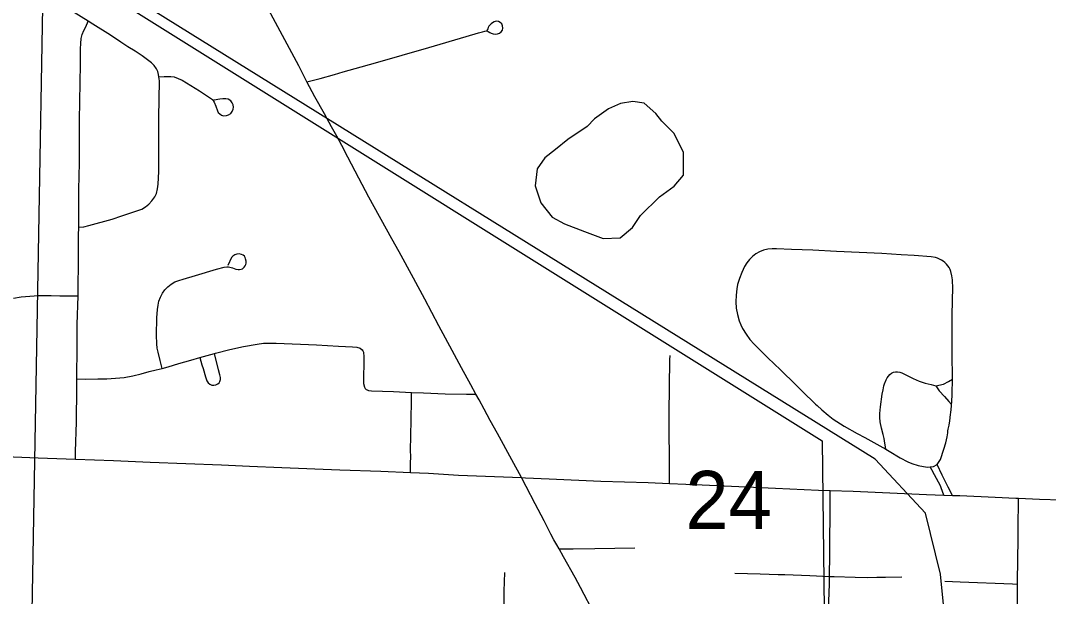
# Model space of a CAD drawing. Extents: x -59 to 43, y 0 to 22.
# Drawn here: x 24.177 to 24.918, y 17.75 to 18.165 of the extents above; entities that cross this region are included whole.
import ezdxf

# ---------------------------------------------------------------- set-up
doc = ezdxf.new("R2010")
doc.units = 0
for name, color, linetype in [('Default', 7, 'Continuous'), ('GM_X_City_Street', 7, 'Continuous'), ('GM_X_Minor_Lake', 7, 'Continuous'), ('GM_X_Rail_Line', 7, 'Continuous'), ('GM_X_Section', 7, 'Continuous'), ('GM_X_Section_Text', 7, 'Continuous'), ('GM_X_State_Route', 7, 'Continuous'), ('GM_X_Township_Road', 7, 'Continuous')]:
    doc.layers.add(name, color=color, linetype=linetype)

msp = doc.modelspace()

# ---------------------------------------------------------------- linework, layer by layer
at = {"layer": 'Default'}
msp.add_lwpolyline([(23.51667, 18.36457), (23.51667, 17.35203), (23.63449, 17.34676), (24.1786, 17.34343), (24.19635, 18.35229)], close=True, dxfattribs=at)
at = {"layer": 'GM_X_City_Street'}
for points in [[(24.21923, 18.01617), (24.22292, 18.01639), (24.22658, 18.01727), (24.24324, 18.02195), (24.2503, 18.02427), (24.26172, 18.02803), (24.26457, 18.02913), (24.2672, 18.03066), (24.26961, 18.03271), (24.27187, 18.03505), (24.27407, 18.0379), (24.27516, 18.04038), (24.27596, 18.0436), (24.27641, 18.04702), (24.27694, 18.05627), (24.27683, 18.06727), (24.27697, 18.08204), (24.27689, 18.09519), (24.27732, 18.12143), (24.27704, 18.12445), (24.27674, 18.12608), (24.27609, 18.12818), (24.27519, 18.13012), (24.27351, 18.13253), (24.27154, 18.13451), (24.2679, 18.1373), (24.26488, 18.13947), (24.25991, 18.14276), (24.25463, 18.14608), (24.24959, 18.14942), (24.24778, 18.15064), (24.24371, 18.15318), (24.24204, 18.15446), (24.22944, 18.16224), (24.22605, 18.16437), (24.21591, 18.17074)], [(24.21681, 17.84902), (24.217, 17.85448), (24.2177, 17.87552), (24.21784, 17.90028), (24.21784, 17.90684), (24.21809, 17.93044), (24.21814, 17.93977), (24.21808, 17.94589), (24.2188, 17.96653), (24.219, 17.99637), (24.2191, 18.00996), (24.21923, 18.01617), (24.21938, 18.0431), (24.21975, 18.0624), (24.21983, 18.07558), (24.21976, 18.09305), (24.22054, 18.13351), (24.22054, 18.14461), (24.22062, 18.14849), (24.22092, 18.1519), (24.22171, 18.15488), (24.22292, 18.15774), (24.22423, 18.16052), (24.22605, 18.16437)], [(24.38365, 18.12071), (24.39323, 18.1233), (24.40359, 18.1261), (24.40968, 18.12792), (24.41844, 18.13029), (24.43301, 18.13436), (24.47142, 18.14549), (24.49835, 18.15341), (24.50729, 18.15605), (24.51005, 18.15675), (24.51188, 18.15725), (24.51309, 18.15748), (24.51424, 18.15699), (24.51531, 18.15638), (24.51646, 18.15587), (24.51787, 18.15545), (24.51942, 18.15519), (24.52096, 18.15526), (24.5224, 18.15577), (24.52361, 18.15672), (24.52444, 18.15801), (24.52479, 18.15952), (24.52464, 18.16106), (24.524, 18.16247), (24.52293, 18.16359), (24.52153, 18.16424), (24.52001, 18.16437), (24.51853, 18.164), (24.51725, 18.16319), (24.51638, 18.16251), (24.5154, 18.16169), (24.51477, 18.16085), (24.51431, 18.1599), (24.51387, 18.15902), (24.51324, 18.15778)], [(24.27704, 18.12445), (24.28067, 18.12465), (24.28285, 18.12463), (24.28546, 18.12458), (24.28796, 18.1243), (24.29093, 18.12319), (24.2937, 18.1219), (24.30611, 18.11432), (24.31554, 18.10803), (24.31604, 18.10735), (24.31674, 18.10605), (24.31792, 18.10318), (24.31911, 18.09986), (24.3197, 18.09875), (24.3208, 18.09773), (24.32215, 18.09685), (24.32358, 18.09638), (24.3256, 18.09646), (24.32718, 18.09689), (24.32873, 18.09793), (24.32984, 18.09931), (24.33039, 18.10098), (24.33063, 18.10252), (24.33047, 18.10415), (24.32987, 18.10573), (24.32869, 18.10712), (24.32694, 18.10819), (24.32528, 18.10863), (24.32309, 18.10862), (24.32092, 18.10838), (24.31684, 18.10747)], [(24.27922, 17.91432), (24.27782, 17.91995), (24.27634, 17.92596), (24.2758, 17.929), (24.27548, 17.93208), (24.27535, 17.93826), (24.27555, 17.95065), (24.276, 17.95679), (24.27635, 17.95986), (24.27698, 17.96288), (24.27803, 17.96577), (24.27948, 17.96848), (24.28134, 17.97095), (24.28349, 17.97313), (24.28588, 17.97505), (24.28856, 17.97658), (24.29144, 17.97768), (24.29439, 17.97862), (24.30333, 17.98119), (24.31835, 17.98592), (24.32406, 17.98737), (24.3258, 17.98751), (24.32714, 17.98741), (24.32996, 17.98683), (24.33231, 17.98589), (24.33412, 17.98549), (24.33502, 17.98549), (24.33622, 17.98571), (24.33712, 17.98611), (24.3385, 17.98727), (24.33915, 17.98814), (24.33955, 17.98922), (24.33973, 17.9902), (24.33977, 17.99168), (24.33947, 17.99335), (24.33908, 17.99422), (24.33853, 17.99508), (24.33763, 17.99584), (24.33643, 17.99649), (24.33478, 17.99685), (24.33321, 17.99671), (24.33172, 17.99613), (24.33032, 17.99519), (24.32939, 17.99412), (24.32667, 17.98842)], [(24.83761, 17.84503), (24.84009, 17.84882), (24.84262, 17.85616), (24.84384, 17.86061), (24.84485, 17.86509), (24.84531, 17.86796), (24.84543, 17.86924), (24.84565, 17.87056), (24.84627, 17.87347), (24.84684, 17.87651), (24.84742, 17.88101), (24.8476, 17.88254), (24.84798, 17.88704), (24.84808, 17.88824), (24.84822, 17.89008), (24.84861, 17.89603), (24.84869, 17.90655), (24.8487, 17.90823), (24.84849, 17.92371), (24.84855, 17.95167), (24.8488, 17.96409), (24.84893, 17.97185), (24.84866, 17.97806), (24.84828, 17.98114), (24.84757, 17.98416), (24.84701, 17.9856), (24.84627, 17.98696), (24.84439, 17.98942), (24.8433, 17.99053), (24.84211, 17.99152), (24.84081, 17.99236), (24.83943, 17.99308), (24.83799, 17.99368), (24.83651, 17.99414), (24.83347, 17.99472), (24.82109, 17.99578), (24.81178, 17.99616), (24.79785, 17.99706), (24.76527, 17.9986), (24.74821, 17.99954), (24.73271, 18.00005), (24.72186, 18.00059), (24.71875, 18.00054), (24.71566, 18.00023), (24.71264, 17.99956), (24.70975, 17.99841), (24.70704, 17.9969), (24.70458, 17.99502), (24.70242, 17.99279), (24.70055, 17.99031), (24.69891, 17.98768), (24.69686, 17.98349), (24.69521, 17.97913), (24.69391, 17.97466), (24.69331, 17.97162), (24.69284, 17.96699), (24.69272, 17.96233), (24.69296, 17.95768), (24.69374, 17.95309), (24.69502, 17.94862), (24.69618, 17.94573), (24.69756, 17.94296), (24.7, 17.93899), (24.70276, 17.93524), (24.70585, 17.93176), (24.7158, 17.92195), (24.72474, 17.91334), (24.73586, 17.90249), (24.74359, 17.8949), (24.74684, 17.89163), (24.75006, 17.88852), (24.75116, 17.8875), (24.75449, 17.8845), (24.75917, 17.88063), (24.76284, 17.87783), (24.76537, 17.87603), (24.7706, 17.8727), (24.78007, 17.86745), (24.78553, 17.86451), (24.79639, 17.85851), (24.80068, 17.85603), (24.8031, 17.85463), (24.81106, 17.84981), (24.81654, 17.84692), (24.81944, 17.84582), (24.82412, 17.84438), (24.83038, 17.84306), (24.83263, 17.8433), (24.83498, 17.84356), (24.83761, 17.84503)], [(24.17221, 17.96499), (24.17763, 17.9659), (24.18409, 17.96645), (24.19015, 17.9668), (24.19934, 17.96686), (24.20553, 17.96673), (24.21171, 17.96664), (24.2188, 17.96653)], [(24.21784, 17.90684), (24.22413, 17.90666), (24.23302, 17.90685), (24.2394, 17.90685), (24.24579, 17.90723), (24.25189, 17.90778), (24.25819, 17.90889), (24.26414, 17.91034), (24.27001, 17.91206), (24.27492, 17.91327), (24.27922, 17.91432), (24.28354, 17.91538), (24.29145, 17.91778), (24.29995, 17.92024), (24.30638, 17.92207), (24.31697, 17.92509), (24.31781, 17.92533), (24.32813, 17.9279), (24.33794, 17.93022), (24.34784, 17.93179), (24.35237, 17.93244), (24.35802, 17.93263), (24.36139, 17.93251), (24.39054, 17.93126), (24.40632, 17.93043), (24.41646, 17.92999), (24.41969, 17.9296), (24.42187, 17.92886), (24.42344, 17.92776), (24.42394, 17.9271), (24.42446, 17.92609), (24.42474, 17.92276), (24.42447, 17.90342), (24.42502, 17.90083), (24.42557, 17.89988), (24.42625, 17.89925), (24.42702, 17.89879), (24.42796, 17.89848), (24.43003, 17.89815), (24.44599, 17.89771), (24.45896, 17.89707), (24.46766, 17.89664), (24.48328, 17.89602), (24.4986, 17.89578), (24.50541, 17.89566)], [(24.30638, 17.92207), (24.30798, 17.91698), (24.30885, 17.91423), (24.31046, 17.90822), (24.31157, 17.90529), (24.31239, 17.904), (24.31359, 17.90297), (24.31505, 17.90228), (24.31648, 17.90214), (24.31807, 17.90239), (24.31935, 17.9032), (24.32036, 17.90405), (24.32098, 17.90499), (24.32135, 17.90624), (24.32129, 17.90775), (24.32098, 17.90962), (24.31984, 17.91342), (24.31697, 17.92509)], [(24.64478, 17.83143), (24.64477, 17.83697), (24.64467, 17.88186), (24.64514, 17.92056), (24.64524, 17.92365)], [(24.80068, 17.85603), (24.79968, 17.86221), (24.79943, 17.86374), (24.79873, 17.86674), (24.7976, 17.87124), (24.79674, 17.87579), (24.79647, 17.87887), (24.79647, 17.88196), (24.79689, 17.88659), (24.79809, 17.89577), (24.79872, 17.89879), (24.79931, 17.9018), (24.79972, 17.90328), (24.80092, 17.90614), (24.80168, 17.90749), (24.80256, 17.90876), (24.80359, 17.90992), (24.80479, 17.91089), (24.80617, 17.91157), (24.80767, 17.91195), (24.8092, 17.91198), (24.81072, 17.91169), (24.81218, 17.91116), (24.82046, 17.90695), (24.82472, 17.90512), (24.82914, 17.90369), (24.83335, 17.90267), (24.83678, 17.90174)], [(24.83678, 17.90174), (24.84217, 17.90306), (24.84582, 17.90501), (24.84869, 17.90655)], [(24.83678, 17.90174), (24.83925, 17.89829), (24.84305, 17.89418), (24.84614, 17.89052), (24.84808, 17.88824)], [(24.45814, 17.8393), (24.45825, 17.84554), (24.45837, 17.85115), (24.45833, 17.85493), (24.45868, 17.87704), (24.45888, 17.89141), (24.45896, 17.89707)], [(24.84253, 17.82303), (24.84054, 17.8282), (24.84, 17.82962), (24.83874, 17.83238), (24.83589, 17.83776), (24.83384, 17.84125), (24.83263, 17.8433)], [(24.84873, 17.82283), (24.84574, 17.8288), (24.84357, 17.83314), (24.84125, 17.8374), (24.83761, 17.84503)], [(24.75783, 17.57509), (24.75775, 17.5809), (24.75755, 17.5963), (24.75766, 17.61436), (24.75805, 17.63606), (24.7582, 17.64534), (24.75857, 17.66365), (24.75905, 17.67897), (24.75936, 17.69707), (24.75975, 17.71576), (24.75976, 17.72499), (24.75984, 17.73114), (24.75964, 17.73728), (24.75976, 17.74655), (24.76007, 17.75889), (24.76013, 17.76445), (24.76035, 17.78052), (24.7604, 17.7866), (24.76046, 17.79422), (24.76061, 17.8051), (24.76064, 17.82032), (24.76066, 17.82639)], [(24.89354, 17.56934), (24.8936, 17.57423), (24.89369, 17.58232), (24.894, 17.60899), (24.89474, 17.64881), (24.89508, 17.6762), (24.89525, 17.69113), (24.89533, 17.69816), (24.89549, 17.73313), (24.89562, 17.75894), (24.89562, 17.76112), (24.89597, 17.79158), (24.89608, 17.80215), (24.89622, 17.81695), (24.89626, 17.82077)], [(24.56525, 17.78433), (24.57097, 17.78438), (24.57545, 17.78441), (24.59109, 17.78465), (24.6199, 17.78508)], [(24.52524, 17.70669), (24.52531, 17.71158), (24.52542, 17.72027), (24.52559, 17.72977), (24.52552, 17.73956), (24.52565, 17.74904), (24.52572, 17.75395), (24.52611, 17.76733)], [(24.69186, 17.76672), (24.7102, 17.76631), (24.72311, 17.76592), (24.728, 17.76579), (24.74587, 17.76505), (24.76013, 17.76445), (24.76359, 17.76431), (24.77851, 17.76388), (24.78777, 17.76371), (24.79434, 17.76383), (24.80047, 17.76395), (24.81223, 17.76408)], [(24.84327, 17.76107), (24.85418, 17.76055), (24.89201, 17.75908), (24.89562, 17.75894)]]:
    msp.add_lwpolyline(points, dxfattribs=at)
at = {"layer": 'GM_X_Minor_Lake'}
msp.add_line((24.58541, 18.08859), (24.57158, 18.07935), dxfattribs=at)
msp.add_lwpolyline([(24.57158, 18.07935), (24.56271, 18.07192), (24.55501, 18.06598), (24.54955, 18.0581), (24.54818, 18.04596), (24.55212, 18.03372), (24.56027, 18.02331), (24.56928, 18.01858), (24.5836, 18.01299), (24.59715, 18.0078), (24.6093, 18.00833), (24.61817, 18.01576), (24.62403, 18.0244), (24.63756, 18.03783), (24.64833, 18.04561), (24.65493, 18.05346), (24.65486, 18.06981), (24.64829, 18.08362), (24.63936, 18.09252), (24.63491, 18.09793), (24.6267, 18.10531), (24.61838, 18.1066), (24.60963, 18.10525), (24.60083, 18.10123), (24.59083, 18.0942), (24.58541, 18.08859)], dxfattribs=at)
at = {"layer": 'GM_X_Rail_Line'}
for points in [[(24.85953, 17.57035), (24.84019, 17.76617), (24.82935, 17.81016), (24.79303, 17.84892), (24.19874, 18.21842), (23.51667, 18.64966)], [(23.51667, 18.64098), (24.21418, 18.20034), (24.75495, 17.86208), (24.75829, 17.57829), (24.85953, 17.57035)]]:
    msp.add_lwpolyline(points, dxfattribs=at)
at = {"layer": 'GM_X_Section'}
msp.add_lwpolyline([(24.19635, 18.35229), (25.1906, 18.3142), (25.19112, 18.29638), (25.18772, 17.31279), (24.42943, 17.3409), (24.1786, 17.34343)], close=True, dxfattribs=at)
at = {"layer": 'GM_X_State_Route'}
msp.add_lwpolyline([(24.5911, 17.73674), (24.58068, 17.75644), (24.5768, 17.76372), (24.56847, 17.77858), (24.56525, 17.78433), (24.56367, 17.78716), (24.56162, 17.79081), (24.5594, 17.79481), (24.55443, 17.80444), (24.54812, 17.81688), (24.54162, 17.82926), (24.53821, 17.83563), (24.53136, 17.84846), (24.52089, 17.86745), (24.51569, 17.8768), (24.51131, 17.88485), (24.50761, 17.89165), (24.50541, 17.89566), (24.50164, 17.90255), (24.49494, 17.91484), (24.48826, 17.92713), (24.47877, 17.94495), (24.4685, 17.96416), (24.46051, 17.97927), (24.45008, 17.99827), (24.44478, 18.00773), (24.42824, 18.03765), (24.42097, 18.05138), (24.41312, 18.0666), (24.40886, 18.07489), (24.4051, 18.08166), (24.40141, 18.08834), (24.39617, 18.09783), (24.38941, 18.11007), (24.38554, 18.11706), (24.38365, 18.12071), (24.37768, 18.13223), (24.35431, 18.17608)], dxfattribs=at)
at = {"layer": 'GM_X_Township_Road'}
for points in [[(24.16021, 17.85099), (24.18989, 17.84998), (24.21681, 17.84902)], [(24.21681, 17.84902), (24.24429, 17.84804), (24.27069, 17.84687), (24.32196, 17.84485), (24.34216, 17.84401), (24.36545, 17.84288), (24.40741, 17.84132), (24.43693, 17.84021), (24.45814, 17.8393)], [(24.45814, 17.8393), (24.47112, 17.83874), (24.49285, 17.83752), (24.53821, 17.83563)], [(24.53821, 17.83563), (24.541, 17.83551), (24.55808, 17.83473), (24.59535, 17.83319), (24.62955, 17.83205), (24.64478, 17.83143)], [(24.64478, 17.83143), (24.66838, 17.83048), (24.72119, 17.82811), (24.75224, 17.82668), (24.76066, 17.82639)], [(24.76066, 17.82639), (24.77711, 17.82582), (24.82994, 17.82343), (24.84253, 17.82303)], [(24.84253, 17.82303), (24.84873, 17.82283), (24.85414, 17.82266), (24.87947, 17.82168), (24.89428, 17.82087), (24.89626, 17.82077)], [(24.89626, 17.82077), (24.91139, 17.82022), (24.92702, 17.81964), (24.93948, 17.81919)]]:
    msp.add_lwpolyline(points, dxfattribs=at)

# ---------------------------------------------------------------- texts
at = {"layer": 'GM_X_Section_Text'}
msp.add_text('24', height=0.041856, rotation=0.00001, dxfattribs=at).set_placement((24.65631, 17.79864))

doc.saveas('drawing.dxf')
